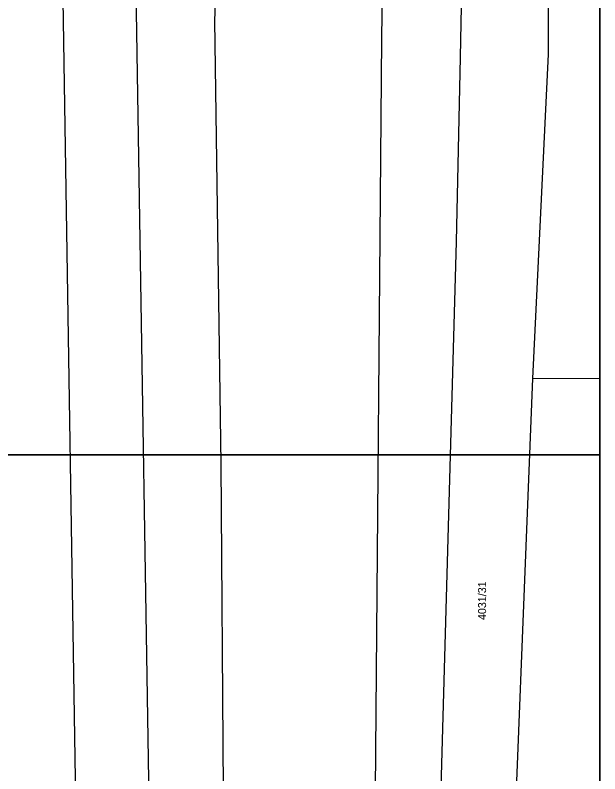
# Model space of a CAD drawing. Extents: x -534410 to -534262, y -1190162 to -1189584.
# Drawn here: x -534323.8 to -534261.6, y -1189828.3 to -1189747.8 of the extents above; entities that cross this region are included whole.
import ezdxf

# ---------------------------------------------------------------- set-up
doc = ezdxf.new("R2010")
doc.units = 0
for name, color, linetype in [('_rámeček', 7, 'Continuous'), ('_rámeček_mřížka', 7, 'Continuous'), ('Hranice parcel', 7, 'Continuous'), ('Parcelní čísla', 7, 'Continuous')]:
    doc.layers.add(name, color=color, linetype=linetype)

msp = doc.modelspace()

# ---------------------------------------------------------------- linework, layer by layer
at = {"layer": '_rámeček'}
msp.add_lwpolyline([(-534410.126, -1190161.97), (-534261.626, -1190161.97), (-534261.626, -1189584.47)], dxfattribs=at)
for points in [[(-534410.126, -1189689.47), (-534261.626, -1189689.47), (-534261.626, -1189794.47), (-534410.126, -1189794.47)], [(-534410.126, -1189794.47), (-534261.626, -1189794.47), (-534261.626, -1189899.47), (-534410.126, -1189899.47)]]:
    msp.add_lwpolyline(points, close=True, dxfattribs=at)
at = {"layer": '_rámeček_mřížka'}
msp.add_line((-534264.626, -1189794.47), (-534261.626, -1189794.47), dxfattribs=at)
msp.add_lwpolyline([(-534410.126, -1190161.97), (-534261.626, -1190161.97), (-534261.626, -1189584.47)], dxfattribs=at)
at = {"layer": 'Hranice parcel'}
msp.add_line((-534261.626, -1189786.398), (-534268.75, -1189786.35), dxfattribs=at)
for points in [[(-534323.08, -1189942.39), (-534320.68, -1189906.36), (-534317.14, -1189842.3), (-534318.66, -1189746.11), (-534316.499, -1189653.713)], [(-534314.47, -1189942.34), (-534311.69, -1189899.83), (-534309.24, -1189848.85), (-534310.92, -1189745.14), (-534308.433, -1189653.713)], [(-534285.48, -1189830.14), (-534284.81, -1189750.3), (-534283.999, -1189688.914)], [(-534268.75, -1189786.35), (-534267.08, -1189751.92), (-534266.881, -1189688.914)], [(-534301.62, -1189830.03), (-534301.89, -1189795.41), (-534302.54, -1189748.37), (-534300.348, -1189689.47)], [(-534284.68, -1189943.89), (-534282.37, -1189910.46), (-534280.12, -1189888.37), (-534278.75, -1189838.65), (-534276.86, -1189771.85), (-534276.43, -1189752.24), (-534275.19, -1189689.29)], [(-534276.35, -1189944.53), (-534272.88, -1189899.59), (-534271.33, -1189851.42), (-534268.75, -1189786.35)]]:
    msp.add_lwpolyline(points, dxfattribs=at)

# ---------------------------------------------------------------- texts
at = {"layer": 'Parcelní čísla'}
msp.add_text('4031/31', height=0.85, rotation=90, dxfattribs=at).set_placement((-534273.717, -1189812.006))

doc.saveas('drawing.dxf')
